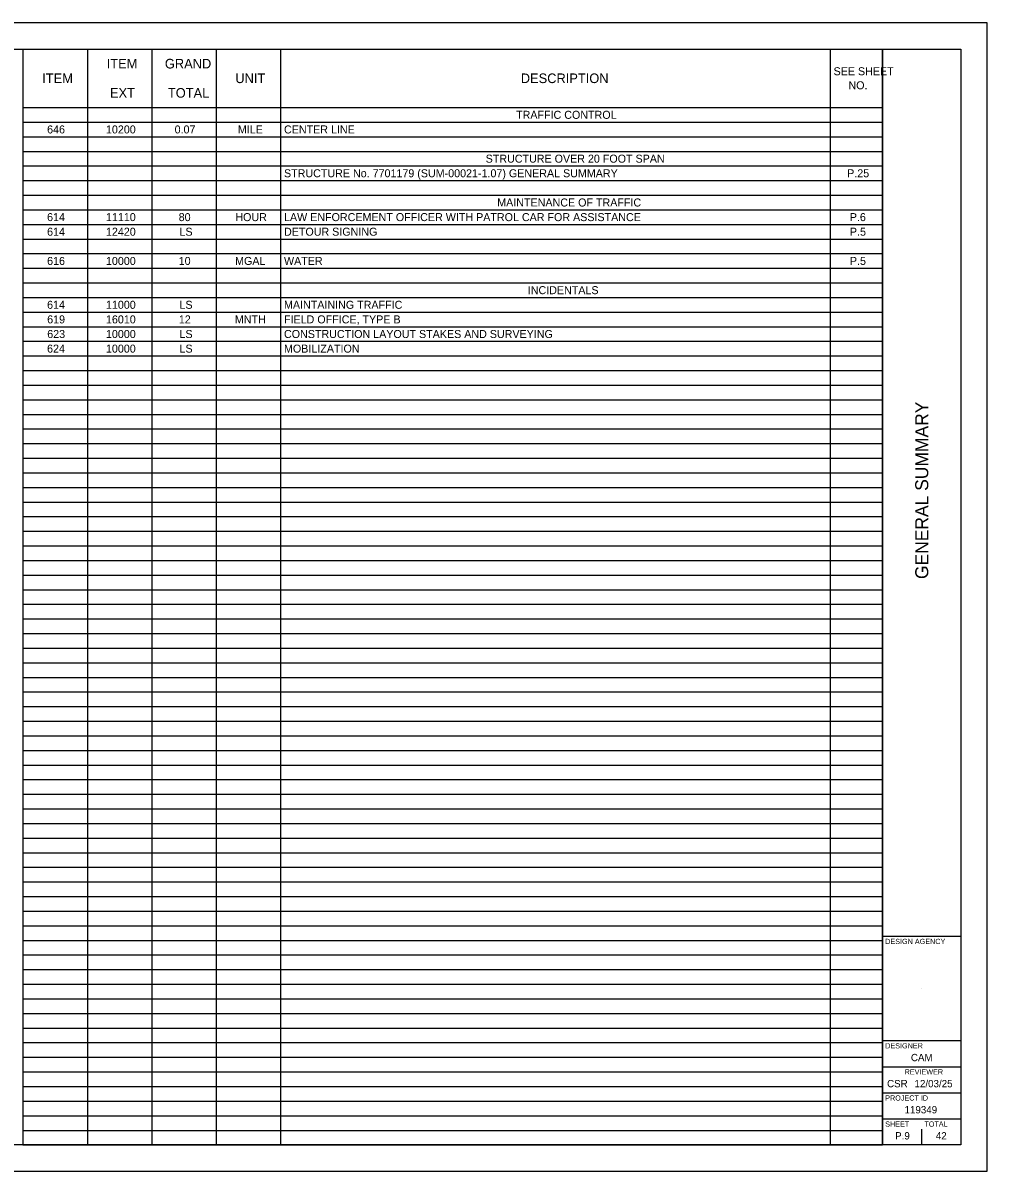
# Model space of a CAD drawing. Extents: x 0 to 34, y 0 to 22.
# Drawn here: x 15.54 to 34, y 0 to 22 of the extents above; entities that cross this region are included whole.
import ezdxf

# ---------------------------------------------------------------- set-up
doc = ezdxf.new("R2010")
doc.units = 0
for name, color, linetype in [('SH_Border', 7, 'Continuous'), ('SH_Cut_Line', 7, 'Continuous'), ('SH_Data', 7, 'Continuous'), ('SH_Text', 7, 'Continuous')]:
    doc.layers.add(name, color=color, linetype=linetype)

msp = doc.modelspace()

# ---------------------------------------------------------------- linework, layer by layer
at = {"layer": 'SH_Border'}
for p, q in [((32, 0.5), (32, 21.5)), ((32, 4.5), (33.5, 4.5)), ((32, 2.5), (33.5, 2.5)), ((32, 2), (33.5, 2)), ((32, 1.5), (33.5, 1.5)), ((32, 1), (33.5, 1))]:
    msp.add_line(p, q, dxfattribs=at)
msp.add_lwpolyline([(1.5, 21.5), (33.5, 21.5), (33.5, 0.5), (1.5, 0.5)], close=True, dxfattribs=at)
at = {"layer": 'SH_Cut_Line'}
msp.add_lwpolyline([(0, 0), (34, 0), (34, 22), (0, 22)], close=True, dxfattribs=at)
at = {"layer": 'SH_Data'}
for p, q in [((32.75, 3.5), (32.75, 3.5)), ((32.375, 0.675), (32.375, 0.675)), ((32.75, 0.5), (32.75, 0.8))]:
    msp.add_line(p, q, dxfattribs=at)
at = {"layer": 'SH_Text'}
for p, q in [((15.535, 21.5), (18.003, 21.5)), ((15.535, 21.5), (15.535, 21.22)), ((16.769, 21.5), (16.769, 21.22)), ((18.003, 21.5), (19.237, 21.5)), ((18.003, 21.5), (18.003, 21.22)), ((19.237, 21.5), (32, 21.5)), ((19.237, 21.5), (19.237, 21.22)), ((20.471, 21.5), (20.471, 21.22)), ((30.997, 21.5), (30.997, 21.22)), ((32, 21.5), (32, 21.22)), ((15.535, 21.22), (15.535, 20.94)), ((16.769, 21.22), (16.769, 20.94)), ((18.003, 21.22), (18.003, 20.94)), ((19.237, 21.22), (19.237, 20.94)), ((20.471, 21.22), (20.471, 20.94)), ((30.997, 21.22), (30.997, 20.94)), ((32, 21.22), (32, 20.94)), ((15.535, 20.94), (15.535, 20.66)), ((16.769, 20.94), (16.769, 20.66)), ((18.003, 20.94), (18.003, 20.66)), ((19.237, 20.94), (19.237, 20.66)), ((20.471, 20.94), (20.471, 20.66)), ((30.997, 20.94), (30.997, 20.66)), ((32, 20.94), (32, 20.66)), ((15.535, 20.66), (15.535, 20.38)), ((16.769, 20.66), (16.769, 20.38)), ((18.003, 20.66), (18.003, 20.38)), ((19.237, 20.66), (19.237, 20.38)), ((20.471, 20.66), (20.471, 20.38)), ((30.997, 20.66), (30.997, 20.38)), ((32, 20.66), (32, 20.38)), ((15.535, 20.38), (18.003, 20.38)), ((15.535, 20.38), (15.535, 20.1)), ((16.769, 20.38), (16.769, 20.1)), ((18.003, 20.38), (19.237, 20.38)), ((18.003, 20.38), (18.003, 20.1)), ((19.237, 20.38), (32, 20.38)), ((19.237, 20.38), (19.237, 20.1)), ((20.471, 20.38), (20.471, 20.1)), ((30.997, 20.38), (30.997, 20.1)), ((32, 20.38), (32, 20.1)), ((15.535, 20.1), (18.003, 20.1)), ((15.535, 20.1), (15.535, 18.7)), ((16.769, 20.1), (16.769, 18.7)), ((18.003, 20.1), (19.237, 20.1)), ((18.003, 20.1), (18.003, 18.7)), ((19.237, 20.1), (32, 20.1)), ((19.237, 20.1), (19.237, 18.7)), ((20.471, 20.1), (20.471, 18.7)), ((30.997, 20.1), (30.997, 18.7)), ((32, 20.1), (32, 18.7)), ((15.535, 19.82), (18.003, 19.82)), ((18.003, 19.82), (19.237, 19.82)), ((19.237, 19.82), (32, 19.82)), ((15.535, 19.54), (18.003, 19.54)), ((18.003, 19.54), (19.237, 19.54)), ((19.237, 19.54), (32, 19.54)), ((15.535, 19.26), (18.003, 19.26)), ((18.003, 19.26), (19.237, 19.26)), ((19.237, 19.26), (32, 19.26)), ((15.535, 18.98), (18.003, 18.98)), ((18.003, 18.98), (19.237, 18.98)), ((19.237, 18.98), (32, 18.98)), ((15.535, 18.7), (18.003, 18.7)), ((15.535, 18.7), (15.535, 18.14)), ((16.769, 18.7), (16.769, 18.14)), ((18.003, 18.7), (19.237, 18.7)), ((18.003, 18.7), (18.003, 18.14)), ((19.237, 18.7), (32, 18.7)), ((19.237, 18.7), (19.237, 18.14)), ((20.471, 18.7), (20.471, 18.14)), ((30.997, 18.7), (30.997, 18.14)), ((32, 18.7), (32, 18.14)), ((15.535, 18.42), (18.003, 18.42)), ((18.003, 18.42), (19.237, 18.42)), ((19.237, 18.42), (32, 18.42)), ((15.535, 18.14), (18.003, 18.14)), ((15.535, 18.14), (15.535, 17.86)), ((16.769, 18.14), (16.769, 17.86)), ((18.003, 18.14), (19.237, 18.14)), ((18.003, 18.14), (18.003, 17.86)), ((19.237, 18.14), (32, 18.14)), ((19.237, 18.14), (19.237, 17.86)), ((20.471, 18.14), (20.471, 17.86)), ((30.997, 18.14), (30.997, 17.86)), ((32, 18.14), (32, 17.86)), ((15.535, 17.86), (18.003, 17.86)), ((15.535, 17.86), (15.535, 17.58)), ((16.769, 17.86), (16.769, 17.58)), ((18.003, 17.86), (19.237, 17.86)), ((18.003, 17.86), (18.003, 17.58)), ((19.237, 17.86), (32, 17.86)), ((19.237, 17.86), (19.237, 17.58)), ((20.471, 17.86), (20.471, 17.58)), ((30.997, 17.86), (30.997, 17.58)), ((32, 17.86), (32, 17.58)), ((15.535, 17.58), (18.003, 17.58)), ((15.535, 17.58), (15.535, 17.3)), ((16.769, 17.58), (16.769, 17.3)), ((18.003, 17.58), (19.237, 17.58)), ((18.003, 17.58), (18.003, 17.3)), ((19.237, 17.58), (32, 17.58)), ((19.237, 17.58), (19.237, 17.3)), ((20.471, 17.58), (20.471, 17.3)), ((30.997, 17.58), (30.997, 17.3)), ((32, 17.58), (32, 17.3)), ((15.535, 17.3), (18.003, 17.3)), ((15.535, 17.3), (15.535, 17.02)), ((16.769, 17.3), (16.769, 17.02)), ((18.003, 17.3), (19.237, 17.3)), ((18.003, 17.3), (18.003, 17.02)), ((19.237, 17.3), (32, 17.3)), ((19.237, 17.3), (19.237, 17.02)), ((20.471, 17.3), (20.471, 17.02)), ((30.997, 17.3), (30.997, 17.02)), ((32, 17.3), (32, 17.02)), ((15.535, 17.02), (18.003, 17.02)), ((15.535, 17.02), (15.535, 16.74)), ((16.769, 17.02), (16.769, 16.74)), ((18.003, 17.02), (19.237, 17.02)), ((18.003, 17.02), (18.003, 16.74)), ((19.237, 17.02), (32, 17.02)), ((19.237, 17.02), (19.237, 16.74)), ((20.471, 17.02), (20.471, 16.74)), ((30.997, 17.02), (30.997, 16.74)), ((32, 17.02), (32, 16.74)), ((15.535, 16.74), (18.003, 16.74)), ((15.535, 16.74), (15.535, 16.18)), ((16.769, 16.74), (16.769, 16.18)), ((18.003, 16.74), (19.237, 16.74)), ((18.003, 16.74), (18.003, 16.18)), ((19.237, 16.74), (32, 16.74)), ((19.237, 16.74), (19.237, 16.18)), ((20.471, 16.74), (20.471, 16.18)), ((30.997, 16.74), (30.997, 16.18)), ((32, 16.74), (32, 16.18)), ((15.535, 16.46), (18.003, 16.46)), ((18.003, 16.46), (19.237, 16.46)), ((19.237, 16.46), (32, 16.46)), ((15.535, 16.18), (18.003, 16.18)), ((15.535, 16.18), (15.535, 15.9)), ((16.769, 16.18), (16.769, 15.9)), ((18.003, 16.18), (19.237, 16.18)), ((18.003, 16.18), (18.003, 15.9)), ((19.237, 16.18), (32, 16.18)), ((19.237, 16.18), (19.237, 15.9)), ((20.471, 16.18), (20.471, 15.9)), ((30.997, 16.18), (30.997, 15.9)), ((32, 16.18), (32, 15.9)), ((15.535, 15.9), (18.003, 15.9)), ((15.535, 15.9), (15.535, 15.62)), ((16.769, 15.9), (16.769, 15.62)), ((18.003, 15.9), (19.237, 15.9)), ((18.003, 15.9), (18.003, 15.62)), ((19.237, 15.9), (32, 15.9)), ((19.237, 15.9), (19.237, 15.62)), ((20.471, 15.9), (20.471, 15.62)), ((30.997, 15.9), (30.997, 15.62)), ((32, 15.9), (32, 15.62)), ((15.535, 15.62), (18.003, 15.62)), ((15.535, 15.62), (15.535, 15.34)), ((16.769, 15.62), (16.769, 15.34)), ((18.003, 15.62), (19.237, 15.62)), ((18.003, 15.62), (18.003, 15.34)), ((19.237, 15.62), (32, 15.62)), ((19.237, 15.62), (19.237, 15.34)), ((20.471, 15.62), (20.471, 15.34)), ((30.997, 15.62), (30.997, 15.34)), ((32, 15.62), (32, 15.34)), ((15.535, 15.34), (18.003, 15.34)), ((15.535, 15.34), (15.535, 14.78)), ((16.769, 15.34), (16.769, 14.78)), ((18.003, 15.34), (19.237, 15.34)), ((18.003, 15.34), (18.003, 14.78)), ((19.237, 15.34), (32, 15.34)), ((19.237, 15.34), (19.237, 14.78)), ((20.471, 15.34), (20.471, 14.78)), ((30.997, 15.34), (30.997, 14.78)), ((32, 15.34), (32, 14.78)), ((15.535, 15.06), (18.003, 15.06)), ((18.003, 15.06), (19.237, 15.06)), ((19.237, 15.06), (32, 15.06)), ((15.535, 14.78), (18.003, 14.78)), ((15.535, 14.78), (15.535, 14.5)), ((16.769, 14.78), (16.769, 14.5)), ((18.003, 14.78), (19.237, 14.78)), ((18.003, 14.78), (18.003, 14.5)), ((19.237, 14.78), (32, 14.78)), ((19.237, 14.78), (19.237, 14.5)), ((20.471, 14.78), (20.471, 14.5)), ((30.997, 14.78), (30.997, 14.5)), ((32, 14.78), (32, 14.5)), ((15.535, 14.5), (18.003, 14.5)), ((15.535, 14.5), (15.535, 14.22)), ((16.769, 14.5), (16.769, 14.22)), ((18.003, 14.5), (19.237, 14.5)), ((18.003, 14.5), (18.003, 14.22)), ((19.237, 14.5), (32, 14.5)), ((19.237, 14.5), (19.237, 14.22)), ((20.471, 14.5), (20.471, 14.22)), ((30.997, 14.5), (30.997, 14.22)), ((32, 14.5), (32, 14.22)), ((15.535, 14.22), (18.003, 14.22)), ((15.535, 14.22), (15.535, 13.94)), ((16.769, 14.22), (16.769, 13.94)), ((18.003, 14.22), (19.237, 14.22)), ((18.003, 14.22), (18.003, 13.94)), ((19.237, 14.22), (32, 14.22)), ((19.237, 14.22), (19.237, 13.94)), ((20.471, 14.22), (20.471, 13.94)), ((30.997, 14.22), (30.997, 13.94)), ((32, 14.22), (32, 13.94)), ((15.535, 13.94), (18.003, 13.94)), ((15.535, 13.94), (15.535, 11.7)), ((16.769, 13.94), (16.769, 11.7)), ((18.003, 13.94), (19.237, 13.94)), ((18.003, 13.94), (18.003, 11.7)), ((19.237, 13.94), (32, 13.94)), ((19.237, 13.94), (19.237, 11.7)), ((20.471, 13.94), (20.471, 11.7)), ((30.997, 13.94), (30.997, 11.7)), ((32, 13.94), (32, 11.7)), ((15.535, 13.66), (18.003, 13.66)), ((18.003, 13.66), (19.237, 13.66)), ((19.237, 13.66), (32, 13.66)), ((15.535, 13.38), (18.003, 13.38)), ((18.003, 13.38), (19.237, 13.38)), ((19.237, 13.38), (32, 13.38)), ((15.535, 13.1), (18.003, 13.1)), ((18.003, 13.1), (19.237, 13.1)), ((19.237, 13.1), (32, 13.1)), ((15.535, 12.82), (18.003, 12.82)), ((18.003, 12.82), (19.237, 12.82)), ((19.237, 12.82), (32, 12.82)), ((15.535, 12.54), (18.003, 12.54)), ((18.003, 12.54), (19.237, 12.54)), ((19.237, 12.54), (32, 12.54)), ((15.535, 12.26), (18.003, 12.26)), ((18.003, 12.26), (19.237, 12.26)), ((19.237, 12.26), (32, 12.26)), ((15.535, 11.98), (18.003, 11.98)), ((18.003, 11.98), (19.237, 11.98)), ((19.237, 11.98), (32, 11.98)), ((15.535, 11.7), (18.003, 11.7)), ((15.535, 11.7), (15.535, 11.42)), ((16.769, 11.7), (16.769, 11.42)), ((18.003, 11.7), (19.237, 11.7)), ((18.003, 11.7), (18.003, 11.42)), ((19.237, 11.7), (32, 11.7)), ((19.237, 11.7), (19.237, 11.42)), ((20.471, 11.7), (20.471, 11.42)), ((30.997, 11.7), (30.997, 11.42)), ((32, 11.7), (32, 11.42)), ((15.535, 11.42), (18.003, 11.42)), ((15.535, 11.42), (15.535, 10.3)), ((16.769, 11.42), (16.769, 10.3)), ((18.003, 11.42), (19.237, 11.42)), ((18.003, 11.42), (18.003, 10.3)), ((19.237, 11.42), (32, 11.42)), ((19.237, 11.42), (19.237, 10.3)), ((20.471, 11.42), (20.471, 10.3)), ((30.997, 11.42), (30.997, 10.3)), ((32, 11.42), (32, 10.3)), ((15.535, 11.14), (18.003, 11.14)), ((18.003, 11.14), (19.237, 11.14)), ((19.237, 11.14), (32, 11.14)), ((15.535, 10.86), (18.003, 10.86)), ((18.003, 10.86), (19.237, 10.86)), ((19.237, 10.86), (32, 10.86)), ((15.535, 10.58), (18.003, 10.58)), ((18.003, 10.58), (19.237, 10.58)), ((19.237, 10.58), (32, 10.58)), ((15.535, 10.3), (18.003, 10.3)), ((15.535, 10.3), (15.535, 10.02)), ((16.769, 10.3), (16.769, 10.02)), ((18.003, 10.3), (19.237, 10.3)), ((18.003, 10.3), (18.003, 10.02)), ((19.237, 10.3), (32, 10.3)), ((19.237, 10.3), (19.237, 10.02)), ((20.471, 10.3), (20.471, 10.02)), ((30.997, 10.3), (30.997, 10.02)), ((32, 10.3), (32, 10.02)), ((15.535, 10.02), (18.003, 10.02)), ((15.535, 10.02), (15.535, 9.74)), ((16.769, 10.02), (16.769, 9.74)), ((18.003, 10.02), (19.237, 10.02)), ((18.003, 10.02), (18.003, 9.74)), ((19.237, 10.02), (32, 10.02)), ((19.237, 10.02), (19.237, 9.74)), ((20.471, 10.02), (20.471, 9.74)), ((30.997, 10.02), (30.997, 9.74)), ((32, 10.02), (32, 9.74)), ((15.535, 9.74), (18.003, 9.74)), ((15.535, 9.74), (15.535, 8.9)), ((16.769, 9.74), (16.769, 8.9)), ((18.003, 9.74), (19.237, 9.74)), ((18.003, 9.74), (18.003, 8.9)), ((19.237, 9.74), (32, 9.74)), ((19.237, 9.74), (19.237, 8.9)), ((20.471, 9.74), (20.471, 8.9)), ((30.997, 9.74), (30.997, 8.9)), ((32, 9.74), (32, 8.9)), ((15.535, 9.46), (18.003, 9.46)), ((18.003, 9.46), (19.237, 9.46)), ((19.237, 9.46), (32, 9.46)), ((15.535, 9.18), (18.003, 9.18)), ((18.003, 9.18), (19.237, 9.18)), ((19.237, 9.18), (32, 9.18)), ((15.535, 8.9), (18.003, 8.9)), ((15.535, 8.9), (15.535, 8.34)), ((16.769, 8.9), (16.769, 8.34)), ((18.003, 8.9), (19.237, 8.9)), ((18.003, 8.9), (18.003, 8.34)), ((19.237, 8.9), (32, 8.9)), ((19.237, 8.9), (19.237, 8.34)), ((20.471, 8.9), (20.471, 8.34)), ((30.997, 8.9), (30.997, 8.34)), ((32, 8.9), (32, 8.34)), ((15.535, 8.62), (18.003, 8.62)), ((18.003, 8.62), (19.237, 8.62)), ((19.237, 8.62), (32, 8.62)), ((15.535, 8.34), (18.003, 8.34)), ((15.535, 8.34), (15.535, 7.5)), ((16.769, 8.34), (16.769, 7.5)), ((18.003, 8.34), (19.237, 8.34)), ((18.003, 8.34), (18.003, 7.5)), ((19.237, 8.34), (32, 8.34)), ((19.237, 8.34), (19.237, 7.5)), ((20.471, 8.34), (20.471, 7.5)), ((30.997, 8.34), (30.997, 7.5)), ((32, 8.34), (32, 7.5)), ((15.535, 8.06), (18.003, 8.06)), ((18.003, 8.06), (19.237, 8.06)), ((19.237, 8.06), (32, 8.06)), ((15.535, 7.78), (18.003, 7.78)), ((18.003, 7.78), (19.237, 7.78)), ((19.237, 7.78), (32, 7.78)), ((15.535, 7.5), (18.003, 7.5)), ((15.535, 7.5), (15.535, 6.94)), ((16.769, 7.5), (16.769, 6.94)), ((18.003, 7.5), (19.237, 7.5)), ((18.003, 7.5), (18.003, 6.94)), ((19.237, 7.5), (32, 7.5)), ((19.237, 7.5), (19.237, 6.94)), ((20.471, 7.5), (20.471, 6.94)), ((30.997, 7.5), (30.997, 6.94)), ((32, 7.5), (32, 6.94)), ((15.535, 7.22), (18.003, 7.22)), ((18.003, 7.22), (19.237, 7.22)), ((19.237, 7.22), (32, 7.22)), ((15.535, 6.94), (18.003, 6.94)), ((15.535, 6.94), (15.535, 6.1)), ((16.769, 6.94), (16.769, 6.1)), ((18.003, 6.94), (19.237, 6.94)), ((18.003, 6.94), (18.003, 6.1)), ((19.237, 6.94), (32, 6.94)), ((19.237, 6.94), (19.237, 6.1)), ((20.471, 6.94), (20.471, 6.1)), ((30.997, 6.94), (30.997, 6.1)), ((32, 6.94), (32, 6.1)), ((15.535, 6.66), (18.003, 6.66)), ((18.003, 6.66), (19.237, 6.66)), ((19.237, 6.66), (32, 6.66)), ((15.535, 6.38), (18.003, 6.38)), ((18.003, 6.38), (19.237, 6.38)), ((19.237, 6.38), (32, 6.38)), ((15.535, 6.1), (18.003, 6.1)), ((15.535, 6.1), (15.535, 4.98)), ((16.769, 6.1), (16.769, 4.98)), ((18.003, 6.1), (19.237, 6.1)), ((18.003, 6.1), (18.003, 4.98)), ((19.237, 6.1), (32, 6.1)), ((19.237, 6.1), (19.237, 4.98)), ((20.471, 6.1), (20.471, 4.98)), ((30.997, 6.1), (30.997, 4.98)), ((32, 6.1), (32, 4.98)), ((15.535, 5.82), (18.003, 5.82)), ((18.003, 5.82), (19.237, 5.82)), ((19.237, 5.82), (32, 5.82)), ((15.535, 5.54), (18.003, 5.54)), ((18.003, 5.54), (19.237, 5.54)), ((19.237, 5.54), (32, 5.54)), ((15.535, 5.26), (18.003, 5.26)), ((18.003, 5.26), (19.237, 5.26)), ((19.237, 5.26), (32, 5.26)), ((15.535, 4.98), (18.003, 4.98)), ((15.535, 4.98), (15.535, 4.7)), ((16.769, 4.98), (16.769, 4.7)), ((18.003, 4.98), (19.237, 4.98)), ((18.003, 4.98), (18.003, 4.7)), ((19.237, 4.98), (32, 4.98)), ((19.237, 4.98), (19.237, 4.7)), ((20.471, 4.98), (20.471, 4.7)), ((30.997, 4.98), (30.997, 4.7)), ((32, 4.98), (32, 4.7)), ((15.535, 4.7), (18.003, 4.7)), ((15.535, 4.7), (15.535, 3.58)), ((16.769, 4.7), (16.769, 3.58)), ((18.003, 4.7), (19.237, 4.7)), ((18.003, 4.7), (18.003, 3.58)), ((19.237, 4.7), (32, 4.7)), ((19.237, 4.7), (19.237, 3.58)), ((20.471, 4.7), (20.471, 3.58)), ((30.997, 4.7), (30.997, 3.58)), ((32, 4.7), (32, 3.58)), ((15.535, 4.42), (18.003, 4.42)), ((18.003, 4.42), (19.237, 4.42)), ((19.237, 4.42), (32, 4.42)), ((15.535, 4.14), (18.003, 4.14)), ((18.003, 4.14), (19.237, 4.14)), ((19.237, 4.14), (32, 4.14)), ((15.535, 3.86), (18.003, 3.86)), ((18.003, 3.86), (19.237, 3.86)), ((19.237, 3.86), (32, 3.86)), ((15.535, 3.58), (18.003, 3.58)), ((15.535, 3.58), (15.535, 3.3)), ((16.769, 3.58), (16.769, 3.3)), ((18.003, 3.58), (19.237, 3.58)), ((18.003, 3.58), (18.003, 3.3)), ((19.237, 3.58), (32, 3.58)), ((19.237, 3.58), (19.237, 3.3)), ((20.471, 3.58), (20.471, 3.3)), ((30.997, 3.58), (30.997, 3.3)), ((32, 3.58), (32, 3.3)), ((15.535, 3.3), (18.003, 3.3)), ((15.535, 3.3), (15.535, 2.18)), ((16.769, 3.3), (16.769, 2.18)), ((18.003, 3.3), (19.237, 3.3)), ((18.003, 3.3), (18.003, 2.18)), ((19.237, 3.3), (32, 3.3)), ((19.237, 3.3), (19.237, 2.18)), ((20.471, 3.3), (20.471, 2.18)), ((30.997, 3.3), (30.997, 2.18)), ((32, 3.3), (32, 2.18)), ((15.535, 3.02), (18.003, 3.02)), ((18.003, 3.02), (19.237, 3.02)), ((19.237, 3.02), (32, 3.02)), ((15.535, 2.74), (18.003, 2.74)), ((18.003, 2.74), (19.237, 2.74)), ((19.237, 2.74), (32, 2.74)), ((15.535, 2.46), (18.003, 2.46)), ((18.003, 2.46), (19.237, 2.46)), ((19.237, 2.46), (32, 2.46)), ((15.535, 2.18), (18.003, 2.18)), ((15.535, 2.18), (15.535, 1.9)), ((16.769, 2.18), (16.769, 1.9)), ((18.003, 2.18), (19.237, 2.18)), ((18.003, 2.18), (18.003, 1.9)), ((19.237, 2.18), (32, 2.18)), ((19.237, 2.18), (19.237, 1.9)), ((20.471, 2.18), (20.471, 1.9)), ((30.997, 2.18), (30.997, 1.9)), ((32, 2.18), (32, 1.9)), ((15.535, 1.9), (18.003, 1.9)), ((15.535, 1.9), (15.535, 0.78)), ((16.769, 1.9), (16.769, 0.78)), ((18.003, 1.9), (19.237, 1.9)), ((18.003, 1.9), (18.003, 0.78)), ((19.237, 1.9), (32, 1.9)), ((19.237, 1.9), (19.237, 0.78)), ((20.471, 1.9), (20.471, 0.78)), ((30.997, 1.9), (30.997, 0.78)), ((32, 1.9), (32, 0.78)), ((15.535, 1.62), (18.003, 1.62)), ((18.003, 1.62), (19.237, 1.62)), ((19.237, 1.62), (32, 1.62)), ((15.535, 1.34), (18.003, 1.34)), ((18.003, 1.34), (19.237, 1.34)), ((19.237, 1.34), (32, 1.34)), ((15.535, 1.06), (18.003, 1.06)), ((18.003, 1.06), (19.237, 1.06)), ((19.237, 1.06), (32, 1.06)), ((15.535, 0.78), (18.003, 0.78)), ((15.535, 0.78), (15.535, 0.5)), ((16.769, 0.78), (16.769, 0.5)), ((18.003, 0.78), (19.237, 0.78)), ((18.003, 0.78), (18.003, 0.5)), ((19.237, 0.78), (32, 0.78)), ((19.237, 0.78), (19.237, 0.5)), ((20.471, 0.78), (20.471, 0.5)), ((30.997, 0.78), (30.997, 0.5)), ((32, 0.78), (32, 0.5)), ((15.535, 0.5), (18.003, 0.5)), ((18.003, 0.5), (19.237, 0.5)), ((19.237, 0.5), (32, 0.5))]:
    msp.add_line(p, q, dxfattribs=at)

# ---------------------------------------------------------------- texts
at = {"layer": 'SH_Data'}
msp.add_text('GENERAL SUMMARY', height=0.25, rotation=90, dxfattribs=at).set_placement((32.875, 11.344))
for s, height, p in [('DESIGN AGENCY', 0.1, (32.05, 4.35)), ('DESIGNER', 0.1, (32.05, 2.35)), ('CAM', 0.14, (32.542, 2.105)), ('REVIEWER', 0.1, (32.422, 1.85)), ('CSR', 0.14, (32.085, 1.605)), ('12/03/25', 0.14, (32.611, 1.605)), ('PROJECT ID', 0.1, (32.05, 1.35)), ('119349', 0.14, (32.42, 1.105)), ('SHEET', 0.1, (32.05, 0.85)), ('TOTAL', 0.1, (32.8, 0.85)), ('P.9', 0.14, (32.24, 0.605)), ('42', 0.14, (33.019, 0.605))]:
    msp.add_text(s, height=height, dxfattribs=at).set_placement(p)
at = {"layer": 'SH_Text'}
for s, height, p in [('ITEM', 0.184, (17.139, 21.128)), ('GRAND', 0.184, (18.253, 21.128)), ('SEE SHEET ', 0.1533, (31.061, 20.998)), ('ITEM', 0.184, (15.905, 20.848)), ('UNIT', 0.184, (19.603, 20.848)), ('DESCRIPTION', 0.184, (25.07, 20.848)), ('EXT', 0.184, (17.202, 20.568)), ('TOTAL', 0.184, (18.311, 20.568)), ('NO.', 0.1533, (31.346, 20.729)), ('TRAFFIC CONTROL', 0.15333, (24.98, 20.163)), ('646', 0.1533, (15.998, 19.883)), ('10200', 0.1533, (17.125, 19.883)), ('0.07', 0.1533, (18.44, 19.883)), ('MILE', 0.1533, (19.651, 19.883)), ('CENTER LINE', 0.15333, (20.535, 19.883)), ('STRUCTURE OVER 20 FOOT SPAN', 0.15333, (24.397, 19.323)), ('STRUCTURE No. 7701179 (SUM-00021-1.07) GENERAL SUMMARY', 0.15333, (20.535, 19.043)), ('P.25', 0.1533, (31.321, 19.043)), ('MAINTENANCE OF TRAFFIC', 0.15333, (24.619, 18.483)), ('614', 0.1533, (15.997, 18.203)), ('11110', 0.1533, (17.125, 18.203)), ('80', 0.1533, (18.518, 18.203)), ('HOUR', 0.1533, (19.603, 18.203)), ('LAW ENFORCEMENT OFFICER WITH PATROL CAR FOR ASSISTANCE', 0.15333, (20.535, 18.203)), ('P.6', 0.1533, (31.371, 18.203)), ('614', 0.1533, (15.997, 17.923)), ('12420', 0.1533, (17.125, 17.923)), ('LS', 0.1533, (18.533, 17.923)), ('DETOUR SIGNING', 0.15333, (20.535, 17.923)), ('P.5', 0.1533, (31.374, 17.923)), ('616', 0.1533, (15.998, 17.363)), ('10000', 0.1533, (17.125, 17.363)), ('10', 0.1533, (18.518, 17.363)), ('MGAL', 0.1533, (19.598, 17.363)), ('WATER', 0.1533, (20.535, 17.363)), ('P.5', 0.1533, (31.374, 17.363)), ('INCIDENTALS', 0.15333, (25.204, 16.803)), ('614', 0.1533, (15.997, 16.523)), ('11000', 0.1533, (17.125, 16.523)), ('LS', 0.1533, (18.533, 16.523)), ('MAINTAINING TRAFFIC', 0.15333, (20.535, 16.523)), ('619', 0.1533, (15.999, 16.243)), ('16010', 0.1533, (17.125, 16.243)), ('12', 0.1533, (18.521, 16.243)), ('MNTH', 0.1533, (19.593, 16.243)), ('FIELD OFFICE, TYPE B', 0.15333, (20.535, 16.243)), ('623', 0.1533, (16, 15.963)), ('10000', 0.1533, (17.125, 15.963)), ('LS', 0.1533, (18.533, 15.963)), ('CONSTRUCTION LAYOUT STAKES AND SURVEYING', 0.15333, (20.535, 15.963)), ('624', 0.1533, (15.997, 15.683)), ('10000', 0.1533, (17.125, 15.683)), ('LS', 0.1533, (18.533, 15.683)), ('MOBILIZATION', 0.15333, (20.535, 15.683))]:
    msp.add_text(s, height=height, dxfattribs=at).set_placement(p)

doc.saveas('drawing.dxf')
